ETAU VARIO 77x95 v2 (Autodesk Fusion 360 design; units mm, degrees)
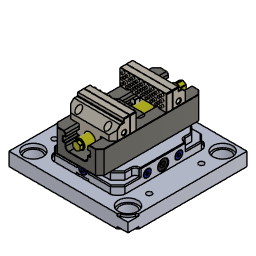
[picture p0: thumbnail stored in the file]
parameter "Ouverture" = 50
base_feature "Base Feature1" OffsetX 0 OffsetY 0 OffsetZ 0
base_feature "Base Feature1"
base_feature "Base Feature1"
base_feature "Base Feature1"
position "Position1"
joint_origin "JointOrigin1" OffsetX 0 OffsetY 0 OffsetZ 0
as_built_joint "As-built1"
as_built_joint "As-built2"
work_axis "WorkAxis1"
work_point "WorkPoint1"
joint_origin "JointOrigin1" OffsetX 0 OffsetY 0 OffsetZ 0
joint "Assemble3" alignOffsetX 0 alignOffsetY 0 alignOffsetZ 25 (= "Ouverture / 2")
joint "Assemble4" alignOffsetX 0 alignOffsetY 0 alignOffsetZ 25 (= "Ouverture / 2")
ground "Ground1"
ground "Terre2"
position "Position3"
ground "Terre3"
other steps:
create_component "CreateComponent1"
create_component "CreateComponent2"
create_component "CreateComponent3"
create_component "CreateComponent4"
joint_origin "JointOrigin4" OffsetX 0 OffsetY 0 OffsetZ 0
joint_origin "JointOrigin5" OffsetX 0 OffsetY 0 OffsetZ 0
